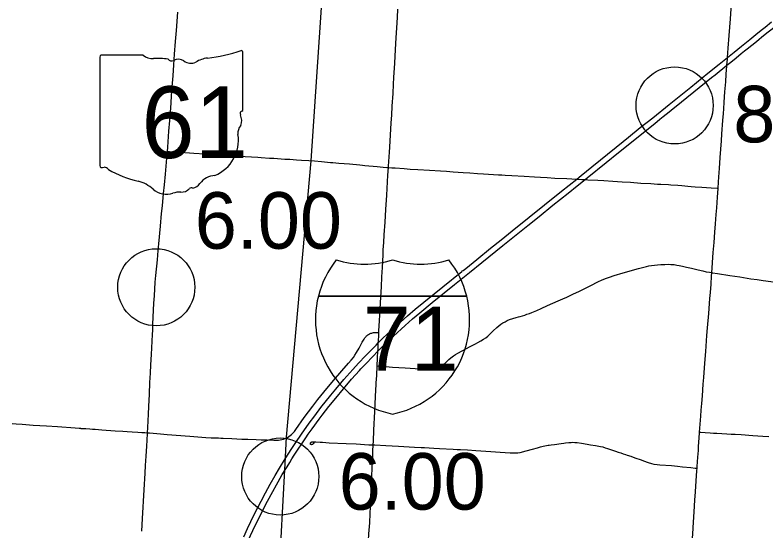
# Model space of a CAD drawing. Extents: x 1813937 to 1948437, y 826606 to 1022856.
# Drawn here: x 1875578 to 1890191, y 884433 to 894473 of the extents above; entities that cross this region are included whole.
import ezdxf

# ---------------------------------------------------------------- set-up
doc = ezdxf.new("R2010")
doc.units = 0
for name, color, linetype in [('Default', 7, 'Continuous'), ('GM_X_County_Road', 7, 'Continuous'), ('GM_X_Interstate_Route', 7, 'Continuous'), ('GM_X_Interstate_Shield', 7, 'Continuous'), ('GM_X_State_Route', 7, 'Continuous'), ('GM_X_State_Shield', 7, 'Continuous'), ('GM_X_Township', 7, 'Continuous'), ('GM_X_Township_Road', 7, 'Continuous')]:
    doc.layers.add(name, color=color, linetype=linetype)

msp = doc.modelspace()

# ---------------------------------------------------------------- linework, layer by layer
at = {"layer": 'Default'}
for centre in [(1888414, 892713), (1878327, 889175), (1880740, 885492)]:
    msp.add_circle(centre, 750, dxfattribs=at)
at = {"layer": 'GM_X_County_Road'}
for points in [[(1889363, 892553), (1889369, 892649), (1889379, 892780), (1889393, 892976), (1889407, 893172), (1889419, 893319), (1889431, 893483), (1889432, 893498), (1889441, 893615), (1889443, 893646), (1889456, 893826), (1889474, 894072), (1889499, 894399), (1889514, 894595), (1889515, 894607)], [(1882846, 891505), (1882848, 891532), (1882853, 891621), (1882866, 891801), (1882872, 891900), (1882899, 892375), (1882909, 892522), (1882920, 892702), (1882935, 892948), (1882945, 893128), (1882952, 893259), (1882969, 893538), (1882984, 893800), (1882998, 894029), (1883010, 894225), (1883020, 894422), (1883028, 894586)], [(1889261, 891099), (1889270, 891226), (1889283, 891405), (1889288, 891487), (1889303, 891700), (1889326, 892027), (1889335, 892158), (1889354, 892420), (1889363, 892553)], [(1882659, 888298), (1882661, 888330), (1882672, 888525), (1882684, 888755), (1882696, 888984), (1882707, 889181), (1882718, 889377), (1882727, 889558), (1882739, 889804), (1882745, 889902), (1882754, 890049), (1882763, 890197), (1882778, 890442), (1882794, 890688), (1882811, 890966), (1882819, 891097), (1882828, 891228), (1882836, 891359), (1882846, 891505)], [(1889137, 889460), (1889143, 889544), (1889152, 889656), (1889166, 889852), (1889181, 890048), (1889196, 890244), (1889210, 890408), (1889222, 890588), (1889232, 890719), (1889248, 890931), (1889261, 891099)], [(1888900, 886354), (1888922, 886667), (1888931, 886782), (1888942, 886913), (1888955, 887060), (1888971, 887288), (1888981, 887419), (1889002, 887697), (1889019, 887926), (1889043, 888237), (1889055, 888384), (1889077, 888662), (1889084, 888760), (1889100, 888956), (1889109, 889070), (1889122, 889233), (1889132, 889394), (1889137, 889460)], [(1882633, 887798), (1882633, 887803), (1882640, 887930), (1882642, 887973), (1882648, 888094), (1882650, 888123), (1882656, 888246)], [(1882656, 888246), (1882659, 888298)], [(1882625, 887645), (1882633, 887798)], [(1882607, 887292), (1882608, 887313), (1882616, 887460), (1882625, 887645)], [(1882549, 886108), (1882553, 886182), (1882563, 886395), (1882581, 886755), (1882594, 887051), (1882607, 887292)], [(1888852, 885654), (1888854, 885686), (1888867, 885866), (1888876, 885997), (1888881, 886079), (1888892, 886242), (1888899, 886340), (1888900, 886354)], [(1882394, 883327), (1882396, 883347), (1882399, 883397), (1882414, 883594), (1882429, 883806), (1882450, 884118), (1882466, 884380), (1882480, 884592), (1882489, 884773), (1882494, 884904), (1882502, 885051), (1882505, 885117), (1882513, 885297), (1882517, 885379), (1882523, 885510), (1882528, 885641), (1882535, 885805), (1882538, 885887), (1882542, 885985), (1882549, 886108)], [(1888677, 882955), (1888685, 883069), (1888692, 883183), (1888703, 883347), (1888718, 883576), (1888726, 883707), (1888734, 883838), (1888745, 884050), (1888750, 884132), (1888766, 884378), (1888781, 884607), (1888793, 884803), (1888810, 885032), (1888820, 885196), (1888836, 885408), (1888848, 885605), (1888852, 885654)]]:
    msp.add_lwpolyline(points, dxfattribs=at)
at = {"layer": 'GM_X_Interstate_Route'}
for points in [[(1889825, 893815), (1889826, 893815), (1889916, 893887), (1890005, 893959), (1890056, 894000), (1890107, 894041), (1890209, 894124), (1890311, 894206), (1890414, 894288), (1890491, 894349), (1890594, 894431), (1890709, 894523), (1890760, 894564), (1890811, 894605), (1890875, 894657), (1891002, 894760), (1891283, 894987), (1891704, 895327), (1891944, 895526), (1892184, 895725), (1892412, 895913), (1892617, 896081)], [(1880029, 884319), (1880104, 884483), (1880167, 884617), (1880254, 884793), (1880366, 885012), (1880450, 885172), (1880545, 885344), (1880642, 885515), (1880726, 885656), (1880838, 885838), (1880850, 885856), (1880952, 886018), (1881042, 886155), (1881153, 886317), (1881305, 886531), (1881412, 886676), (1881531, 886833), (1881724, 887078), (1881818, 887192), (1881977, 887379), (1882150, 887576), (1882261, 887697), (1882396, 887840), (1882604, 888050), (1882648, 888094), (1882743, 888189), (1882887, 888323), (1883009, 888433), (1883218, 888617), (1883367, 888746), (1883531, 888882), (1884271, 889481), (1884280, 889495), (1884296, 889501), (1884348, 889542), (1884565, 889717), (1884833, 889933), (1885037, 890098), (1885255, 890272), (1886214, 891044), (1886508, 891280), (1886597, 891352), (1886801, 891518), (1887273, 891899), (1887414, 892012), (1887516, 892095), (1887745, 892281), (1887989, 892474), (1888309, 892731), (1888437, 892834), (1888731, 893071), (1889063, 893338), (1889280, 893514), (1889443, 893646), (1889573, 893751), (1889714, 893864), (1889879, 893999), (1890032, 894123), (1890122, 894195), (1890173, 894236), (1890301, 894339)], [(1889131, 893254), (1889201, 893310), (1889432, 893498), (1889507, 893558), (1889609, 893641), (1889711, 893723), (1889775, 893774), (1889825, 893815)], [(1882941, 888223), (1883168, 888431), (1883316, 888562), (1883453, 888679), (1883694, 888877), (1884129, 889226), (1884422, 889463), (1884665, 889659), (1885074, 889988), (1885559, 890379), (1885777, 890554), (1886045, 890770), (1886339, 891006), (1886518, 891149), (1886670, 891271), (1886710, 891303), (1887081, 891602), (1887324, 891796), (1888026, 892363), (1888128, 892446), (1888192, 892497), (1888307, 892589), (1888345, 892620), (1888549, 892785), (1888893, 893064), (1889131, 893254)], [(1882310, 887585), (1882404, 887688), (1882540, 887830), (1882640, 887930), (1882807, 888097), (1882926, 888210), (1882941, 888223)], [(1880118, 884246), (1880206, 884440), (1880290, 884618), (1880378, 884795), (1880453, 884941), (1880561, 885143), (1880696, 885387), (1880778, 885529), (1880834, 885622), (1880872, 885684), (1880924, 885767), (1880968, 885837), (1881012, 885906), (1881102, 886043), (1881147, 886111), (1881239, 886247), (1881286, 886315), (1881324, 886368), (1881362, 886422), (1881498, 886607), (1881557, 886686), (1881687, 886855), (1881821, 887020), (1881968, 887197), (1882129, 887384), (1882282, 887555), (1882310, 887585)]]:
    msp.add_lwpolyline(points, dxfattribs=at)
at = {"layer": 'GM_X_Interstate_Shield'}
for p, q in [((1881482, 889003), (1884368, 889003)), ((1884368, 889003), (1881482, 889003)), ((1884368, 889003), (1881482, 889003))]:
    msp.add_line(p, q, dxfattribs=at)
for centre, start, end in [((1883300, 888544), 141.669, 165.8066), ((1882377, 891500), 253.0091, 286.9909), ((1883473, 891500), 253.0091, 286.9909), ((1882550, 888544), 14.1934, 38.331), ((1883300, 888544), 165.8066, 258.463), ((1882550, 888544), 281.537, 14.1934)]:
    msp.add_arc(centre, 1875, start, end, dxfattribs=at)
at = {"layer": 'GM_X_State_Route'}
msp.add_lwpolyline([(1878044, 884431), (1878059, 884676), (1878091, 885233), (1878111, 885560), (1878119, 885708), (1878131, 885887), (1878142, 886083), (1878148, 886198), (1878155, 886329), (1878156, 886344), (1878162, 886443), (1878175, 886705), (1878183, 886852), (1878194, 887096), (1878205, 887324), (1878214, 887504), (1878223, 887668), (1878232, 887864), (1878254, 888257), (1878257, 888339), (1878263, 888454), (1878281, 888863), (1878290, 889010), (1878307, 889272), (1878318, 889402), (1878350, 889712), (1878365, 889892), (1878377, 890022), (1878408, 890365), (1878432, 890610), (1878446, 890757), (1878469, 891002), (1878484, 891165), (1878504, 891377), (1878531, 891688), (1878543, 891817), (1878550, 891900), (1878574, 892210), (1878591, 892423), (1878609, 892668), (1878615, 892766), (1878625, 892897), (1878638, 893077), (1878654, 893289), (1878670, 893502), (1878685, 893714), (1878704, 893959), (1878720, 894172), (1878746, 894531)], dxfattribs=at)
at = {"layer": 'GM_X_State_Shield'}
for p, q in [((1880013, 892638), (1880013, 893744)), ((1877229, 893655), (1877229, 891542)), ((1878072, 893692), (1877256, 893692)), ((1880013, 892639), (1880013, 892638))]:
    msp.add_line(p, q, dxfattribs=at)
for centre, radius, start, end in [((1879022, 896573), 2953, 275.8445, 288.9065), ((1879982, 893749), 31, 351.8621, 97.738), ((1877261, 893660), 32.3, 98.1301, 188.1301), ((1878266, 893937), 313, 231.6195, 271.1119), ((1878370, 892505), 1123, 80.4867, 94.9883), ((1878625, 893671), 90.3, 219.7921, 297.1024), ((1878757, 893426), 188, 54.4667, 119.1411), ((1879398, 893046), 594, 97.3462, 120.7689), ((1878999, 893761), 226, 233.8562, 294.8282), ((1880006, 892557), 48, 107.944, 210.337), ((1879980, 892634), 33.2, 289.6038, 7.7341), ((1879701, 892418), 288, 340.033, 23.6496), ((1880124, 892176), 210, 136.8065, 186.9296), ((1879187, 892035), 739, 292.3089, 8.9858), ((1877261, 891537), 32.5, 171.9584, 258.3066), ((1877266, 891754), 248, 267.339, 280.6039), ((1877317, 891420), 89.5, 29.7484, 93.2717), ((1878448, 893319), 2132, 240.4129, 257.1985), ((1879498, 890949), 404, 94.4031, 142.5768), ((1877812, 890593), 667, 47.1842, 75.836), ((1879013, 891047), 63.5, 65.7517, 132.6484), ((1878986, 891337), 239, 282.8732, 323.2771), ((1878533, 891410), 423, 230.7004, 286.2918), ((1878778, 890679), 348, 85.6951, 111.2099), ((1878809, 891251), 226, 268.777, 315.5493)]:
    msp.add_arc(centre, radius, start, end, dxfattribs=at)
at = {"layer": 'GM_X_Township'}
msp.add_lwpolyline([(1880714, 883463), (1880836, 885744), (1880863, 886256), (1881338, 891636), (1881703, 897023), (1881803, 900282), (1881806, 900375), (1881918, 903829), (1881985, 905459), (1882074, 908232), (1882082, 908847), (1882260, 912507), (1887758, 913255), (1888309, 913332)], dxfattribs=at)
at = {"layer": 'GM_X_Township_Road'}
for points in [[(1878543, 891817), (1878585, 891814), (1878666, 891809), (1878797, 891801), (1879059, 891785), (1879272, 891770), (1879403, 891762), (1879534, 891754), (1879730, 891741), (1879910, 891730), (1880058, 891720), (1880303, 891704), (1880368, 891699), (1880532, 891689), (1880614, 891684), (1880826, 891670), (1880925, 891665), (1881055, 891655), (1881154, 891649)], [(1881154, 891649), (1881297, 891639), (1881407, 891632), (1881544, 891621), (1881718, 891605), (1881766, 891600), (1881881, 891590), (1882085, 891574), (1882289, 891556), (1882342, 891549), (1882386, 891544), (1882623, 891524), (1882741, 891513), (1882816, 891506), (1882846, 891505)], [(1882846, 891505), (1882909, 891501), (1882975, 891497), (1883154, 891483), (1883269, 891476), (1883416, 891468), (1883645, 891455), (1883858, 891440), (1883973, 891431), (1884103, 891422), (1884300, 891409), (1884431, 891399), (1884578, 891389), (1884693, 891381), (1884791, 891375), (1884888, 891370), (1884986, 891364), (1885051, 891360), (1885117, 891357), (1885248, 891349), (1885487, 891338), (1885690, 891324), (1885805, 891318), (1885936, 891310), (1886083, 891300), (1886313, 891292), (1886508, 891280), (1886607, 891275), (1886670, 891271), (1886722, 891268), (1886919, 891257), (1887033, 891250), (1887213, 891238), (1887393, 891228), (1887557, 891217), (1887753, 891203), (1887953, 891192), (1888081, 891184), (1888146, 891181), (1888293, 891172), (1888342, 891167), (1888473, 891159), (1888555, 891153), (1888668, 891142), (1888733, 891137), (1888815, 891131), (1888946, 891124), (1889126, 891110), (1889240, 891101), (1889261, 891099)], [(1882625, 887645), (1882633, 887644), (1882698, 887639), (1882796, 887631), (1882927, 887622), (1883172, 887606), (1883368, 887592), (1883462, 887585), (1883565, 887574), (1883647, 887569), (1883695, 887570), (1883744, 887574), (1883776, 887580), (1883792, 887585), (1883807, 887591), (1883822, 887598), (1883836, 887606), (1883850, 887614), (1883877, 887634), (1883901, 887656), (1883972, 887724), (1884020, 887769), (1884057, 887801), (1884109, 887841), (1884150, 887868), (1884192, 887894), (1884279, 887941), (1884438, 888025), (1884540, 888077), (1884583, 888100), (1884640, 888131), (1884696, 888165), (1884737, 888193), (1884776, 888223), (1884824, 888267), (1884882, 888325), (1884953, 888393), (1884990, 888425), (1885029, 888455), (1885071, 888481), (1885114, 888504), (1885158, 888526), (1885203, 888545), (1885265, 888567), (1885328, 888586), (1885377, 888599), (1885408, 888608), (1885454, 888620), (1885499, 888635), (1885537, 888649), (1885590, 888667), (1885632, 888682), (1885670, 888696), (1885730, 888723), (1885819, 888765), (1885938, 888819), (1886044, 888865), (1886149, 888911), (1886239, 888951), (1886313, 888984), (1886432, 889038), (1886506, 889072), (1886550, 889093), (1886682, 889159), (1886770, 889204), (1886931, 889284), (1886991, 889311), (1887067, 889343), (1887144, 889371), (1887237, 889402), (1887410, 889453), (1887709, 889539), (1887867, 889582), (1887915, 889594), (1887964, 889601), (1888078, 889613), (1888143, 889618), (1888225, 889621), (1888291, 889622), (1888340, 889620), (1888405, 889615), (1888454, 889608), (1888502, 889599), (1888566, 889585), (1888646, 889566), (1888741, 889544), (1888869, 889513), (1888964, 889492), (1889028, 889478), (1889095, 889466), (1889137, 889460)], [(1889137, 889460), (1889151, 889457), (1889248, 889441), (1889491, 889404), (1889685, 889375), (1889896, 889342), (1890021, 889324), (1890138, 889306), (1890284, 889284), (1890430, 889264), (1890592, 889238), (1890786, 889208), (1890883, 889197), (1890981, 889190), (1891079, 889184), (1891161, 889183), (1891226, 889184), (1891324, 889189), (1891487, 889197), (1891749, 889210), (1891913, 889220), (1892190, 889241), (1892321, 889253), (1892395, 889260)], [(1880865, 886247), (1880880, 886254), (1880908, 886271), (1880935, 886290), (1880960, 886311), (1880983, 886334), (1881016, 886371), (1881046, 886410), (1881207, 886638), (1881374, 886863), (1881473, 886994), (1881586, 887135), (1881775, 887363), (1881936, 887549), (1882068, 887695), (1882122, 887758), (1882162, 887810), (1882190, 887851), (1882224, 887907), (1882272, 887993), (1882336, 888108), (1882370, 888164), (1882388, 888191), (1882409, 888216), (1882421, 888228), (1882433, 888239), (1882446, 888249), (1882460, 888258), (1882474, 888266), (1882489, 888273), (1882504, 888279), (1882520, 888285), (1882536, 888289), (1882552, 888292), (1882584, 888296), (1882617, 888297), (1882659, 888298)], [(1875526, 886521), (1875604, 886516), (1875719, 886509), (1875931, 886494), (1876193, 886478), (1876405, 886463), (1876749, 886437), (1876825, 886433), (1876850, 886431), (1876861, 886430), (1876867, 886430), (1876872, 886429), (1876879, 886429), (1876956, 886424), (1877035, 886419), (1877083, 886416), (1877137, 886412), (1877268, 886402), (1877529, 886384), (1877676, 886373), (1877758, 886368), (1877856, 886363), (1877970, 886355), (1878048, 886351), (1878103, 886347), (1878156, 886344)], [(1878156, 886344), (1878197, 886342), (1878409, 886323), (1878539, 886312), (1878980, 886279), (1879290, 886254), (1879394, 886248), (1879442, 886245), (1879496, 886243), (1879540, 886242), (1879583, 886240), (1879599, 886240), (1879632, 886237), (1879795, 886230), (1879992, 886222), (1880106, 886219), (1880270, 886211), (1880368, 886207), (1880429, 886205)], [(1888900, 886354), (1888924, 886353), (1889005, 886348), (1889104, 886342), (1889169, 886339), (1889234, 886336), (1889332, 886330), (1889429, 886324), (1889511, 886318), (1889593, 886314), (1889707, 886307), (1889936, 886293), (1890133, 886280), (1890247, 886273)], [(1880429, 886205), (1880482, 886204), (1880613, 886199), (1880660, 886199), (1880692, 886199), (1880708, 886200), (1880741, 886205), (1880773, 886212), (1880804, 886222), (1880850, 886240), (1880865, 886247)], [(1881406, 886145), (1881389, 886132), (1881379, 886125), (1881374, 886121), (1881365, 886116), (1881361, 886115), (1881357, 886113), (1881353, 886113), (1881350, 886112), (1881346, 886112), (1881341, 886113), (1881337, 886114), (1881334, 886116), (1881331, 886118), (1881328, 886121), (1881326, 886125), (1881325, 886129), (1881324, 886132), (1881324, 886134), (1881325, 886138), (1881326, 886142), (1881327, 886144), (1881331, 886151), (1881334, 886154), (1881338, 886158), (1881340, 886160), (1881345, 886162), (1881351, 886165), (1881359, 886168), (1881367, 886169), (1881374, 886170), (1881383, 886170), (1881400, 886169), (1881432, 886167), (1881514, 886161), (1881563, 886159), (1881694, 886151), (1882022, 886135), (1882219, 886126), (1882465, 886111), (1882549, 886108)], [(1882549, 886108), (1882579, 886106), (1882792, 886095), (1883038, 886083), (1883251, 886071), (1883349, 886065), (1883480, 886058), (1883546, 886055), (1883726, 886046), (1883841, 886039), (1884103, 886026), (1884185, 886021), (1884250, 886017), (1884381, 886009), (1884544, 885998), (1884740, 885988), (1884838, 885981), (1885019, 885969), (1885215, 885954), (1885281, 885951), (1885330, 885951), (1885362, 885954), (1885411, 885963), (1885522, 885991), (1885649, 886024), (1885744, 886052), (1885807, 886071), (1885854, 886083), (1885918, 886096), (1885950, 886102), (1885970, 886104), (1886014, 886110), (1886074, 886117), (1886121, 886123), (1886162, 886129), (1886208, 886134), (1886255, 886140), (1886292, 886145), (1886354, 886153), (1886403, 886157), (1886436, 886158), (1886469, 886157), (1886518, 886153), (1886599, 886142), (1886712, 886120), (1886776, 886109), (1886873, 886095), (1886906, 886091), (1886938, 886086), (1886970, 886079), (1887018, 886067), (1887065, 886053), (1887110, 886039), (1887208, 886005), (1887265, 885985), (1887315, 885969), (1887367, 885951), (1887414, 885935), (1887457, 885921), (1887491, 885910), (1887561, 885886), (1887638, 885859), (1887761, 885814), (1887807, 885798), (1887900, 885765), (1887963, 885747), (1888011, 885736), (1888075, 885725), (1888124, 885718), (1888354, 885704), (1888468, 885694), (1888566, 885684), (1888729, 885666), (1888811, 885658), (1888852, 885654)]]:
    msp.add_lwpolyline(points, dxfattribs=at)

# ---------------------------------------------------------------- texts
at = {"layer": 'Default'}
for s, p in [('8.00', (1889555, 891995)), ('6.00', (1879077, 889925)), ('6.00', (1881876, 884848))]:
    msp.add_text(s, height=1100, dxfattribs=at).set_placement(p)
at = {"layer": 'GM_X_Interstate_Shield'}
msp.add_text('71', height=1250, dxfattribs=at).set_placement((1882348, 887550))
at = {"layer": 'GM_X_State_Shield'}
msp.add_text('61', height=1392.2, dxfattribs=at).set_placement((1878039, 891691))

doc.saveas('drawing.dxf')
